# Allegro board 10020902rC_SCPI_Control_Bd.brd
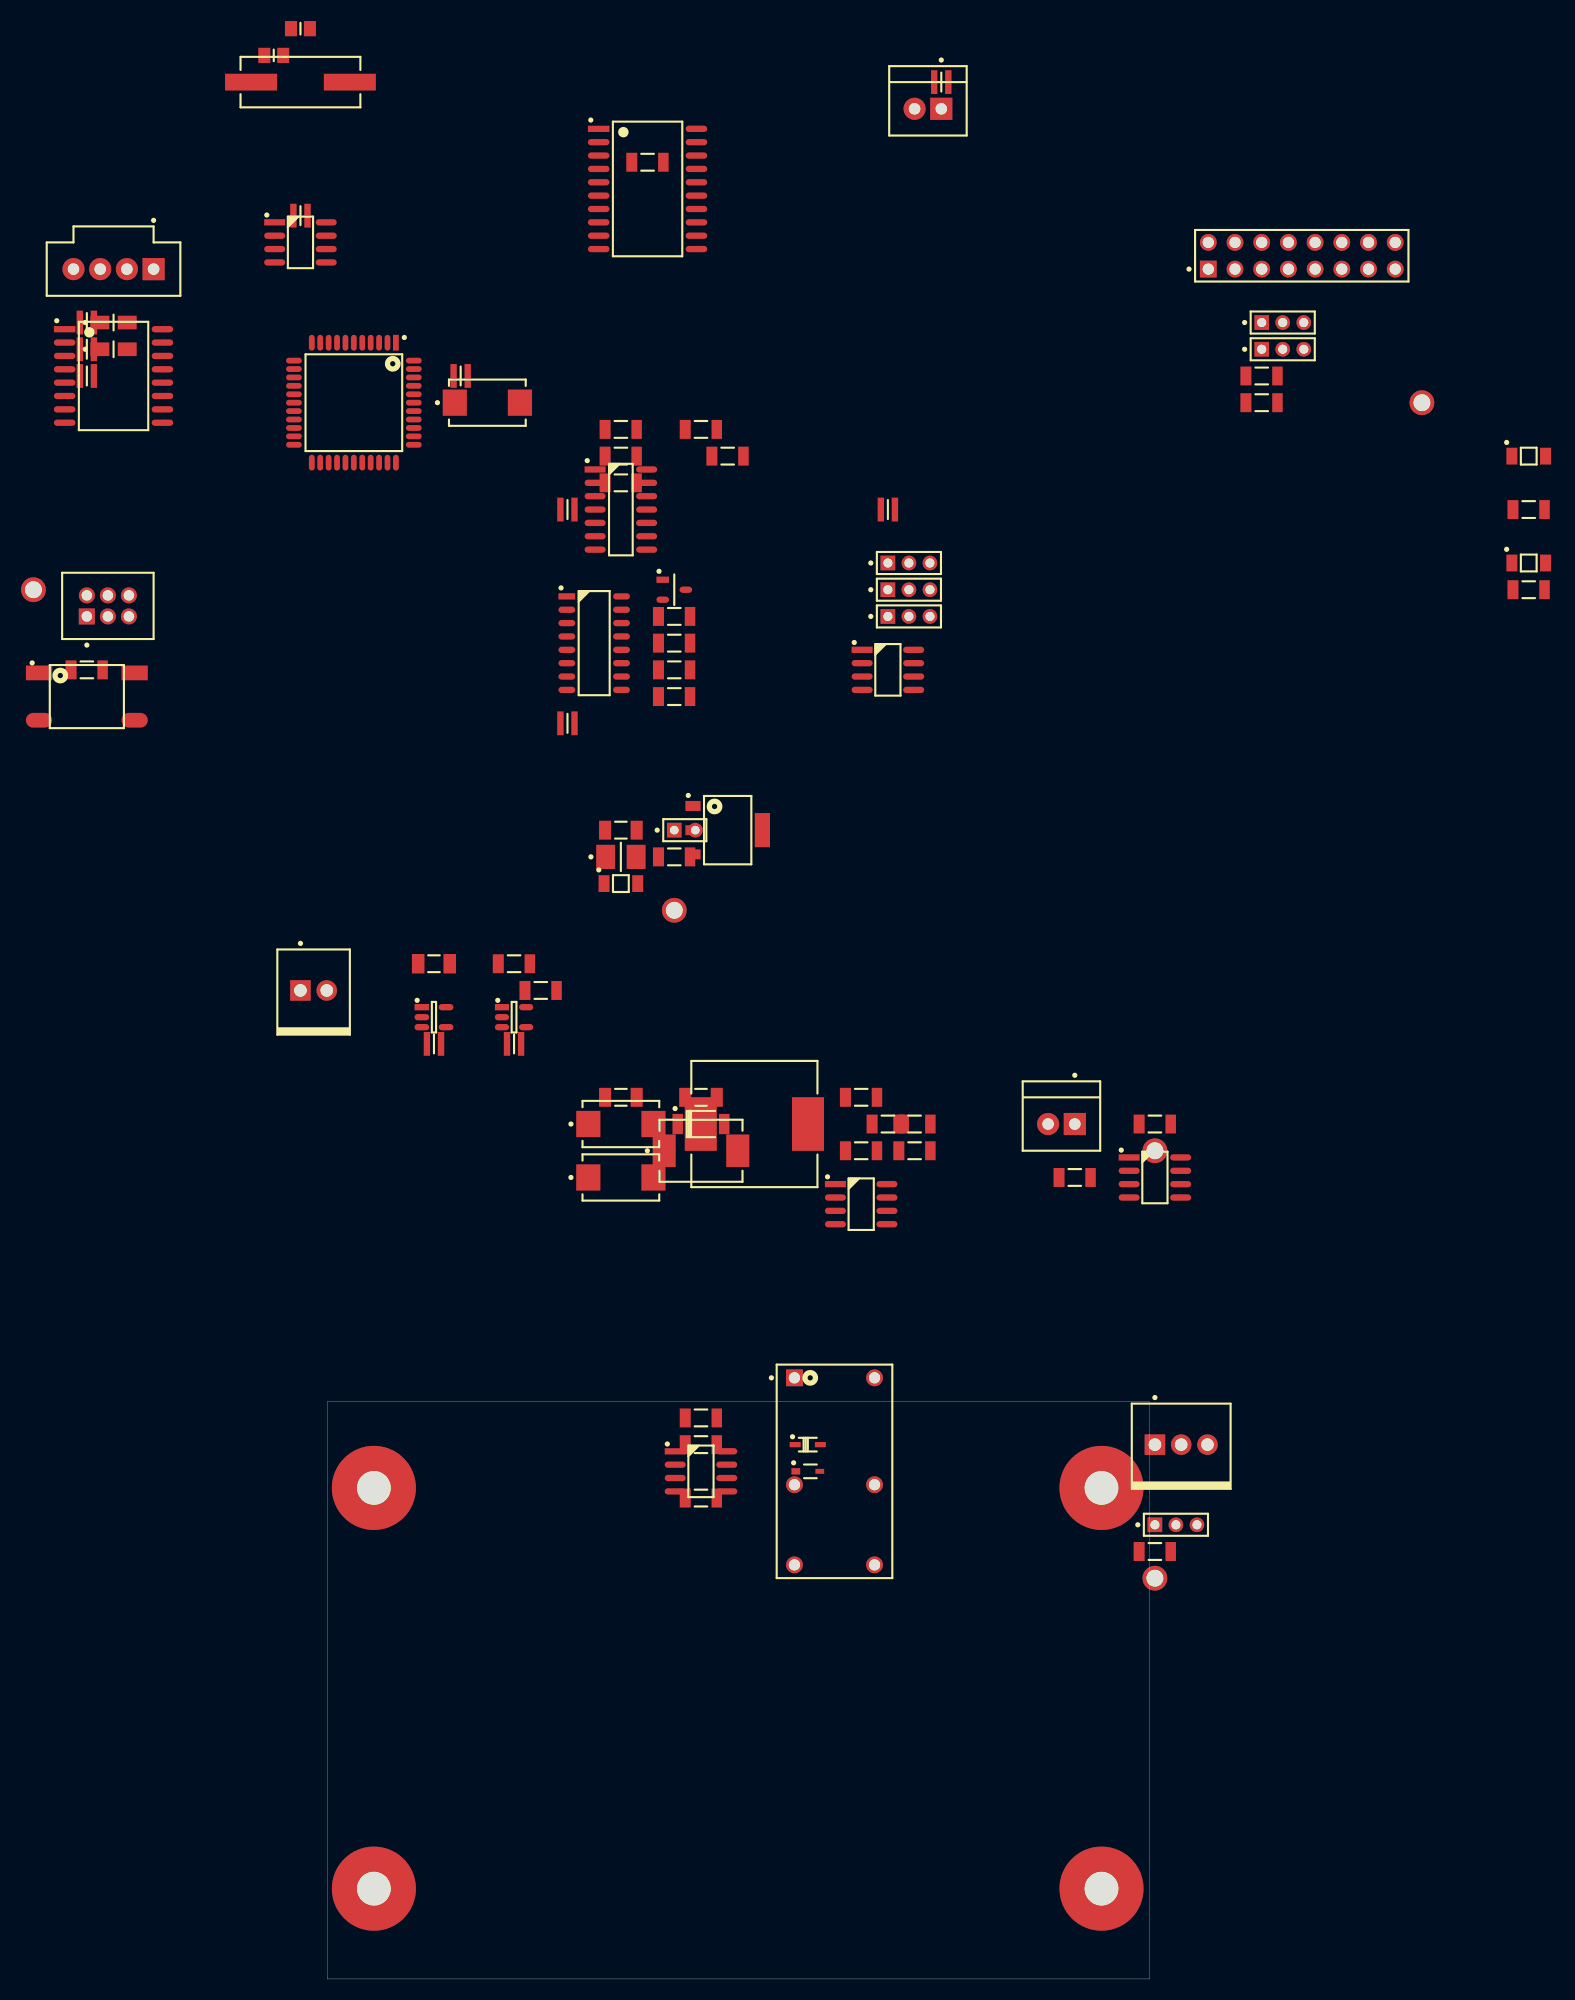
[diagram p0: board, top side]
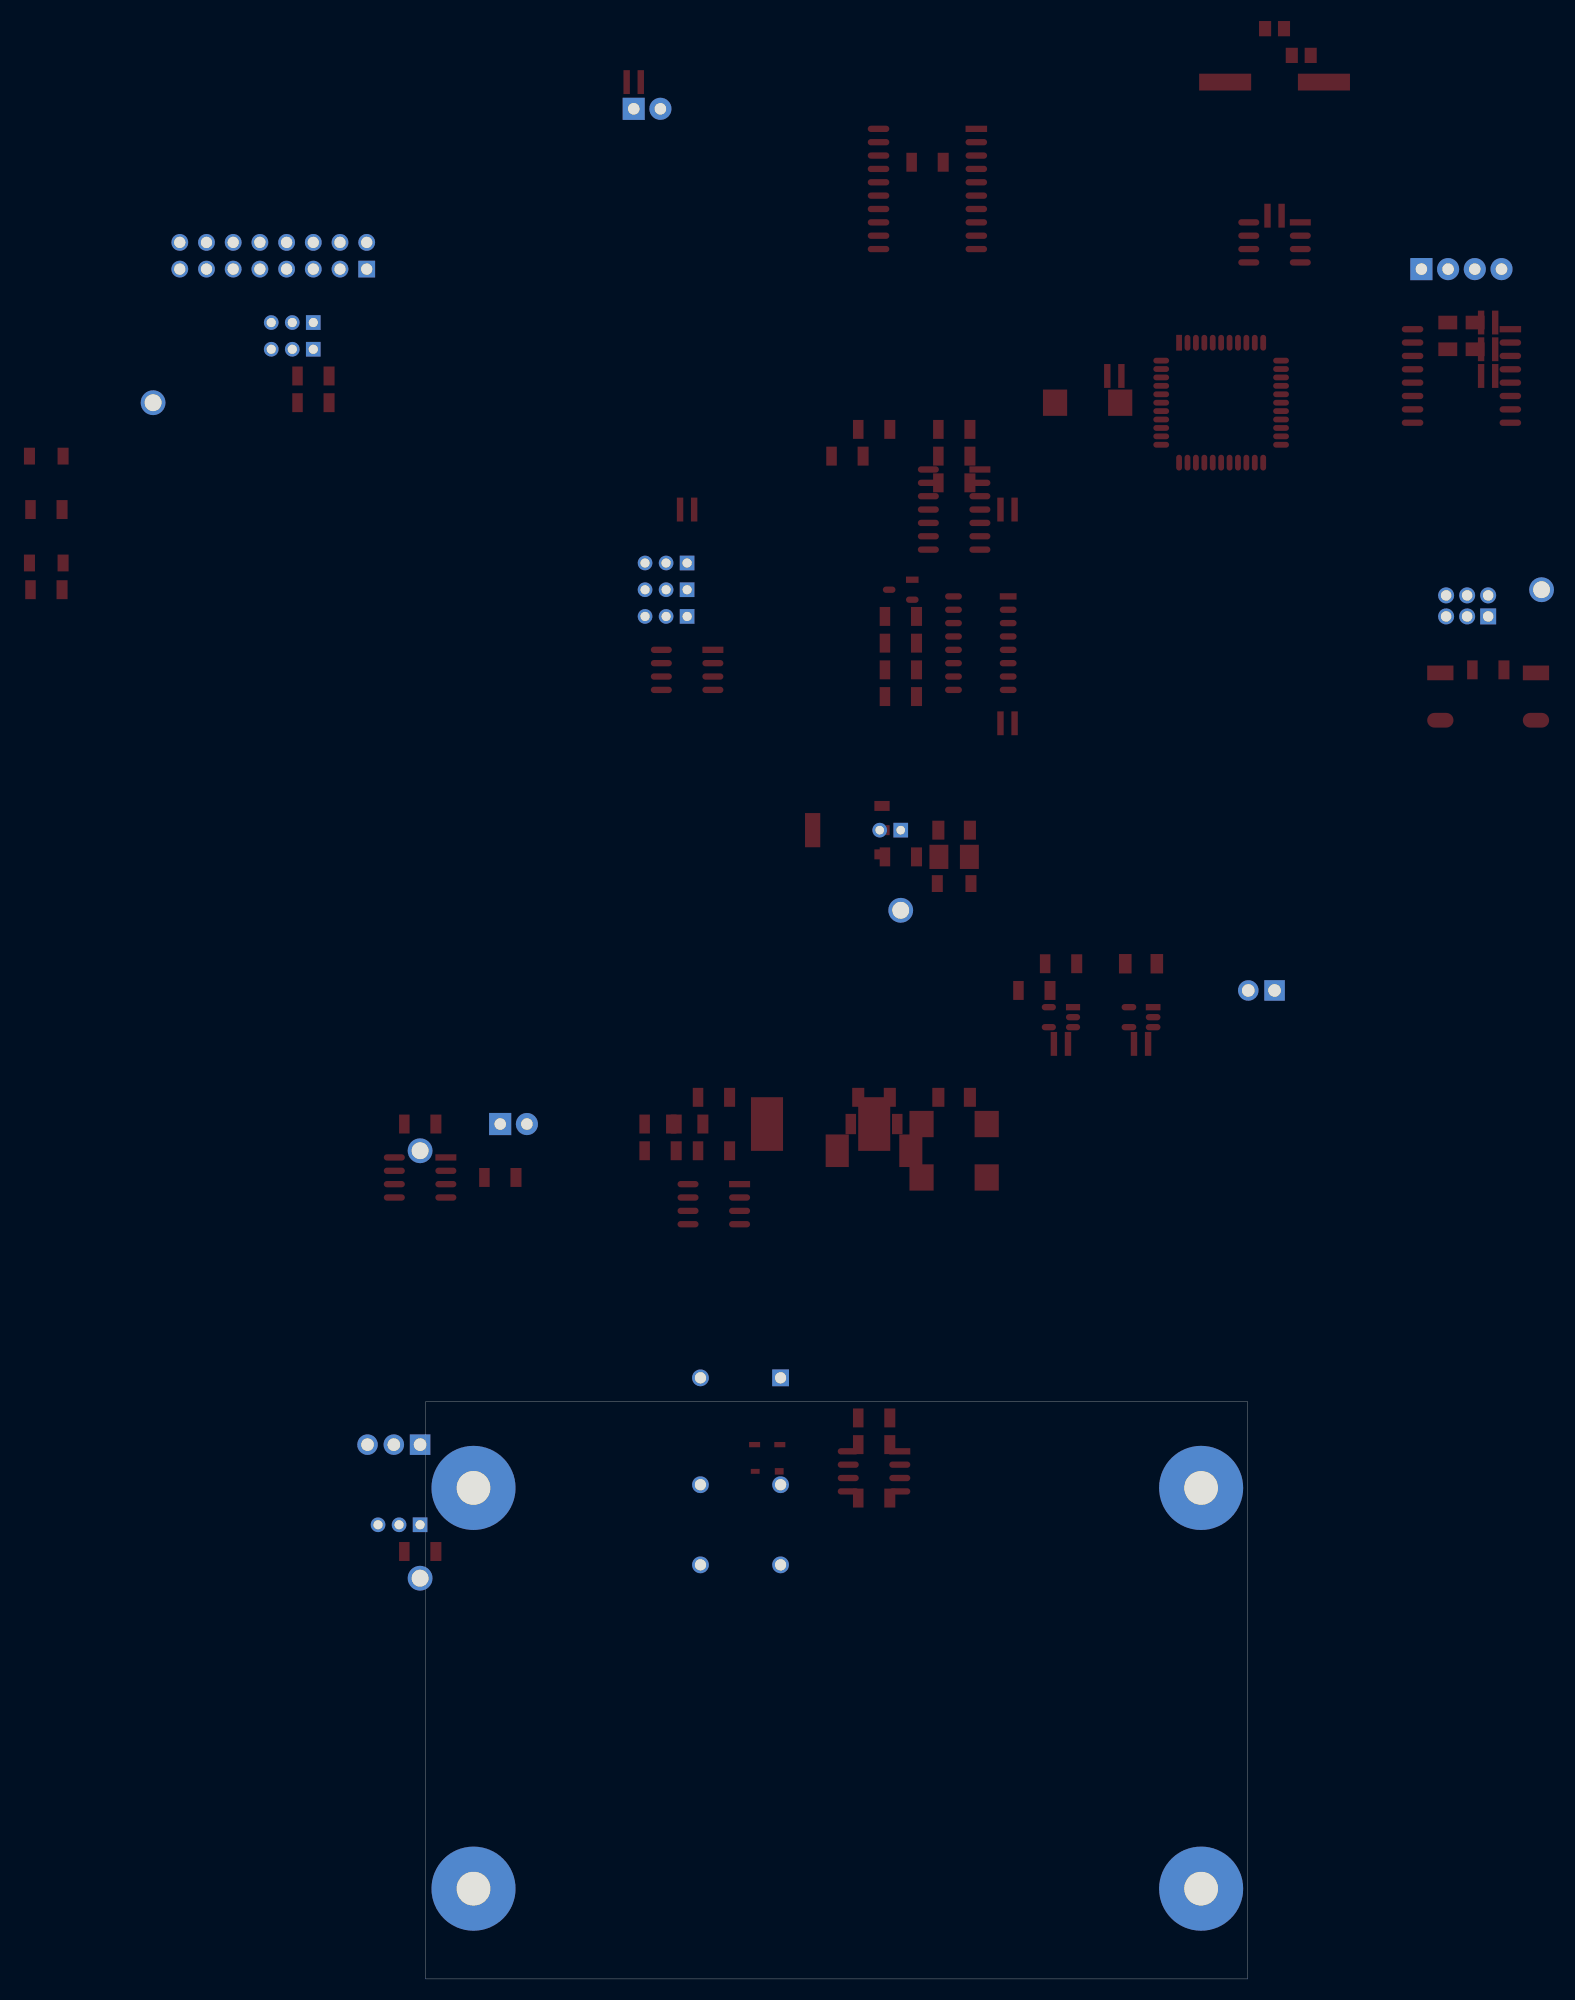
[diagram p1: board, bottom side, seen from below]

Outline 78.23 x 54.86 mm; copper layers: TOP, BOTTOM. Coordinates in mm from the lower left corner of the outline.
Outline path: 0,54.86 0,0 78.23,0 78.23,54.86 0,54.86

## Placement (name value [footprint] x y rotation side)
C1  0.1uF  [CAPC1320X76N]  12.7 152.4 0 top
C2  15pF  [CAPC2012X88N]  -2.54 185.42 0 top
C3  15pF  [CAPC2012X88N]  -5.08 182.88 0 top
C4  0.1uF  [CAPC1320X76N]  -22.86 157.48 0 top
C5  0.1uF  [CAPC1320X76N]  -22.86 154.94 0 top
C6  0.1uF  [CAPC1320X76N]  -22.86 152.4 0 top
C7  0.1uF  [CAPMP3216X180N]  -20.32 157.48 0 top
C8  0.1uF  [CAPMP3216X180N]  -20.32 154.94 0 top
C9  10uF  [CAPMP7343X310N]  15.24 149.86 0 top
C10  0.1uF  [CAPC1320X76N]  -2.54 167.64 0 top
C11  0.1uF  [CAPC1320X76N]  53.34 139.7 0 top
C12  0.1uF  [CAPC1320X76N]  22.86 139.7 0 top
C13  0.1uF  [CAPC1320X76N]  22.86 119.38 0 top
C14  0.1uF  [CAPC1320X76N]  58.42 180.34 0 top
C15  1.0uF  [CAPC3216X110N]  27.94 109.22 0 top
C16  10uF  [CAPMP3528X120N]  27.94 106.68 0 top
C17  0.1uF  [CAPC1320X76N]  10.16 88.9 0 top
C18  0.10uF  [CAPC3216X180N]  27.94 83.82 0 top
C19  100uF  [CAPMP7343X430N]  27.94 81.28 0 top
C20  68uF  [CAPMP7343X310N]  27.94 76.2 0 top
C21  0.10uF  [CAPC3216X180N]  35.56 83.82 0 top
C22  0.1uF  [CAPC1320X76N]  17.78 88.9 0 top
D1  LTST-C150KGKT  [LED_LTST-C150XXX]  114.3 144.78 0 top
D2  LTST-C150KGKT  [LED_LTST-C150XXX]  114.3 134.62 0 top
D3  LTST-C150KGKT  [LED_LTST-C150XXX]  27.94 104.14 0 top
D4  PMEG3050EP,115  [SODFL4725X110N]  35.56 81.28 0 top
D5  B550C-13-F  [DIOM7959X250N]  35.56 78.74 0 top
D6  BZX384-C3V3,115  [SOD2513X110N]  45.72 50.8 0 top
D7  DB2J31700L  [SODFL2513X80N]  45.72 48.26 0 top
J1  68602-116HLF  [HDRV16W64P254_2X8_858H]  83.82 162.56 0 top
J2  87831-0620  [MOLEX_87831-0620]  -22.86 129.54 0 top
J3  70543-0003  [MOLEX_70543-4PIN]  -20.32 162.56 0 top
J4  70543-0001  [MOLEX_70543-2PIN]  58.42 177.8 0 top
J5  1881558  [PHOENIX_1881558]  -2.54 93.98 0 top
J6  70543-0001  [MOLEX_70543-2PIN]  71.12 81.28 0 top
J7  1881561  [PHOENIX_1881561]  78.74 50.8 0 top
JP2  951103-8622-AR  [HDRV3W50P200_1X3_H590]  88.9 157.48 0 top
JP3  951103-8622-AR  [HDRV3W50P200_1X3_H590]  88.9 154.94 0 top
JP4  951103-8622-AR  [HDRV3W50P200_1X3_H590]  53.34 134.62 0 top
JP5  951103-8622-AR  [HDRV3W50P200_1X3_H590]  53.34 132.08 0 top
JP6  951103-8622-AR  [HDRV3W50P200_1X3_H590]  53.34 129.54 0 top
JP7  951102-8622-AR  [HDRV2W50P200_1X2_H590]  33.02 109.22 0 top
JP8  951103-8622-AR  [HDRV3W50P200_1X3_H590]  78.74 43.18 0 top
K1  DSP2A-DC12V  [RELAY_DSP2A-NIL-XXXX]  48.26 48.26 0 top
L1  27uH  [IND_74770127]  40.64 81.28 0 top
NOREF  -  [unnamed]  4.45 8.59 0 top
NOREF#2  -  [unnamed]  73.66 8.59 0 top
NOREF#3  -  [unnamed]  4.45 46.69 0 top
NOREF#4  -  [#2]  -50.8 -76.2 0 top
NOREF#5  -  [unnamed]  73.66 46.69 0 top
Q1  BC847CLT1G  [SOT95P237X111-3N_132]  33.02 132.08 0 top
R1  10.0K  [RESC3216X60N]  27.94 147.32 0 top
R2  10.0K  [RESC3216X60N]  27.94 144.78 0 top
R3  10.0K  [RESC3216X60N]  27.94 142.24 0 top
R4  10.0K  [RESC3216X60N]  -22.86 124.46 0 top
R5  1.00K  [RESC3216X60N]  88.9 152.4 0 top
R6  3.32K  [RESC3216X60N]  33.02 129.54 0 top
R7  6.81K  [RESC3216X60N]  33.02 124.46 0 top
R8  110  [RESC3216X60N]  114.3 139.7 0 top
R9  100.0K  [RESC3216X60N]  88.9 149.86 0 top
R10  1.00K  [RESC3216X60N]  33.02 127 0 top
R11  10.0K  [RESC3216X60N]  33.02 121.92 0 top
R13  110  [RESC3216X60N]  114.3 132.08 0 top
R14  100.0K  [RESC3216X60N]  30.48 172.72 0 top
R15  10.0K  [RESC3216X60N]  35.56 147.32 0 top
R16  10.0K  [RESC3216X60N]  38.1 144.78 0 top
R17  59  [RESC3216X60N]  33.02 106.68 0 top
R18  0.02  [RESC3216X89N]  10.16 96.52 0 top
R19  121.0K  [RESC3216X60N]  17.78 96.52 0 top
R20  22.1K  [RESC3216X60N]  20.32 93.98 0 top
R21  10.0K  [RESC3216X60N]  71.12 76.2 0 top
R22  1.00M  [RESC3216X60N]  50.8 78.74 0 top
R23  TBD  [RESC3216X60N]  50.8 83.82 0 top
R24  10.0K  [RESC3216X60N]  78.74 81.28 0 top
R25  383.0K  [RESC3216X60N]  53.34 81.28 0 top
R26  36.5K  [RESC3216X60N]  55.88 81.28 0 top
R27  13.3K  [RESC3216X60N]  55.88 78.74 0 top
R28  100.0K  [RESC3216X60N]  78.74 40.64 0 top
R29  10.0K  [RESC3216X60N]  35.56 53.34 0 top
R30  10.0K  [RESC3216X60N]  35.56 50.8 0 top
R31  10.0K  [RESC3216X60N]  35.56 45.72 0 top
SW1  SWT6-V2M  [SW_SWT6-M]  -22.86 121.92 0 top
TP1  YELLOW  [TP_KEYSTONE_5000S_COMP]  33.02 101.6 0 top
TP2  RED  [TP_KEYSTONE_5000S_COMP]  -27.94 132.08 0 top
TP3  BLACK  [TP_KEYSTONE_5000S_COMP]  104.14 149.86 0 top
TP4  ORANGE  [TP_KEYSTONE_5000S_COMP]  78.74 78.74 0 top
TP5  GREEN  [TP_KEYSTONE_5000S_COMP]  78.74 38.1 0 top
U1  SN74LS07D  [SOIC127P600X175-14N]  27.94 139.7 0 top
U2  PIC24FJ64GA104-I/PT  [QFP80P1200X1200X120-44N]  2.54 149.86 270 top
U3  74HC4050D,653  [SOIC127P600X175-16N]  25.4 127 0 top
U4  MAX3232IDWR  [SOIC127P1030X265-16N]  -20.32 152.4 0 top
U5  DS3234S#  [SOIC127P1032X265-20N]  30.48 170.18 0 top
U6  SST25VF080B-80-4I-SAE  [SOIC127P600X175-8N]  -2.54 165.1 0 top
U7  24AA01-I/SN  [SOIC127P600X175-8N]  53.34 124.46 0 top
U8  MIC5209-3.3YS  [SOT230P700X180-4N]  38.1 109.22 0 top
U9  MAX4372FEUK+T  [SOT95P280X145-5N]  10.16 91.44 0 top
U10  AD8603AUJZ  [SOT95P280X100-5N]  17.78 91.44 0 top
U11  MAX5035DASA+  [SOIC127P600X175-8N]  50.8 73.66 0 top
U12  IRF7309TRPBF  [SOIC127P600X175-8N]  78.74 76.2 0 top
U13  IRF7309TRPBF  [SOIC127P600X175-8N]  35.56 48.26 0 top
Y1  3.6864MHz  [XTAL1140X480X430N]  -2.54 180.34 0 top

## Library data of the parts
C1-C6 C10-C15 C17 C18 C21 C22 = CAP
C7-C9 C16 C19 C20 = CAP_P
D1-D3 = LED
D4 D5 = DIODE_SCHOTTKY
D6 = DIODE_ZENER
D7 = DIODE
J1 = CON16
J2 = CON6
J3 = CON4
J4-J6 = CON2
J7 = CON3
JP2-JP6 JP8 = JUMPER3PIN_CENTER-TAP
JP7 = JUMPER
K1 = RELAY_DSP2A-NIL-XXXX
L1 = IND_FERRITE
Q1 = BJT_NPN_BEC
R1-R11 R13-R31 = RES
SW1 = SW_SPST_13_24
TP1-TP5 = TESTPOINT
U1 = SN74LS07
U2 = PIC24FJxxGA104
U3 = 74HC4050
U4 = MAX3232
U5 = DS3234Sx
U6 = SST25VF080B
U7 = 24AA01SN
U8 = MIC5209-x.xxS
U9 = MAX4372xEUK-T_SYM-MOD1
U10 = AD8603
U11 = MAX5035
U12 U13 = IRF7309
Y1 = CRYSTAL

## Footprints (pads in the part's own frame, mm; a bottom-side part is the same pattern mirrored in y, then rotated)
CAPC1320X76N
  rect 0.61x2.271 smd: 1(-0.671,0) 2(0.671,0)
CAPC2012X88N
  rect 1.151x1.45 smd: 1(-0.899,0) 2(0.899,0)
CAPC3216X110N
  rect 1.151x1.801 smd: 1(-1.501,0) 2(1.501,0)
CAPC3216X180N
  rect 1.151x1.801 smd: 1(-1.501,0) 2(1.501,0)
CAPMP3216X180N
  rect 1.801x1.3 smd: 1(-1.3,0) 2(1.3,0)
CAPMP3528X120N
  rect 1.801x2.301 smd: 1(-1.45,0) 2(1.45,0)
CAPMP7343X310N
  rect 2.301x2.499 smd: 1(-3.099,0) 2(3.099,0)
CAPMP7343X430N
  rect 2.301x2.499 smd: 1(-3.099,0) 2(3.099,0)
DIOM7959X250N
  rect 2.2x3.099 smd: A(3.5,0) C(-3.5,0)
HDRV2W50P200_1X2_H590
  rect 1.397x1.397 hole 0.813: 1(0,0)
  round 1.397 hole 0.813: 2(1.999,0)
HDRV3W50P200_1X3_H590
  rect 1.397x1.397 hole 0.864: 1(0,0)
  round 1.397 hole 0.864: 2(1.999,0) 3(4,0)
HDRV16W64P254_2X8_858H
  rect 1.6x1.6 hole 1.067: 1(0,0)
  round 1.6 hole 1.067: 2(0,2.54) 3(2.54,0) 4(2.54,2.54) 5(5.08,0) 6(5.08,2.54) 7(7.62,0) 8(7.62,2.54) 9(10.16,0) 10(10.16,2.54) 11(12.7,0) 12(12.7,2.54) 13(15.24,0) 14(15.24,2.54) 15(17.78,0) 16(17.78,2.54)
IND_74770127
  rect 3.051x5.1 smd: 1(-5.1,0) 2(5.1,0)
LED_LTST-C150XXX
  rect 1.049x1.6 smd: A(1.6,0) C(-1.6,0)
MOLEX_70543-2PIN
  rect 2.108x2.108 hole 1.092: 1(0,0)
  round 2.108 hole 1.092: 2(-2.54,0)
MOLEX_70543-4PIN
  rect 2.108x2.108 hole 1.092: 1(3.81,0)
  round 2.108 hole 1.092: 2(1.27,0) 3(-1.27,0) 4(-3.81,0)
MOLEX_87831-0620
  rect 1.524x1.524 hole 0.991: 1(0,0)
  round 1.524 hole 0.991: 2(0,1.999) 3(1.999,0) 4(1.999,1.999) 5(4,0) 6(4,1.999)
PHOENIX_1881558
  rect 1.956x1.956 hole 1.194: 1(0,0)
  round 1.956 hole 1.194: 2(2.499,0)
PHOENIX_1881561
  rect 1.956x1.956 hole 1.194: 1(0,0)
  round 1.956 hole 1.194: 2(2.499,0) 3(5.001,0)
QFP80P1200X1200X120-44N
  rect 1.501x0.551 smd: 1(-5.7,4)
  oval 1.501x0.551 smd: 2(-5.7,3.2) 3(-5.7,2.4) 4(-5.7,1.6) 5(-5.7,0.8) 6(-5.7,0) 7(-5.7,-0.8) 8(-5.7,-1.6) 9(-5.7,-2.4) 10(-5.7,-3.2) 11(-5.7,-4) 23(5.7,-4) 24(5.7,-3.2) 25(5.7,-2.4) 26(5.7,-1.6) 27(5.7,-0.8) 28(5.7,0) 29(5.7,0.8) 30(5.7,1.6) 31(5.7,2.4) 32(5.7,3.2) 33(5.7,4)
  oval 0.551x1.501 smd: 12(-4,-5.7) 13(-3.2,-5.7) 14(-2.4,-5.7) 15(-1.6,-5.7) 16(-0.8,-5.7) 17(0,-5.7) 18(0.8,-5.7) 19(1.6,-5.7) 20(2.4,-5.7) 21(3.2,-5.7) 22(4,-5.7) 34(4,5.7) 35(3.2,5.7) 36(2.4,5.7) 37(1.6,5.7) 38(0.8,5.7) 39(0,5.7) 40(-0.8,5.7) 41(-1.6,5.7) 42(-2.4,5.7) 43(-3.2,5.7) 44(-4,5.7)
RELAY_DSP2A-NIL-XXXX
  rect 1.6x1.6 hole 1.067: 1(-3.81,8.89)
  round 1.6 hole 1.067: 5(-3.81,-1.27) 8(-3.81,-8.89) 9(3.81,-8.89) 12(3.81,-1.27) 16(3.81,8.89)
RESC3216X60N
  rect 1.049x1.801 smd: 1(-1.501,0)
  rect 1.001x1.801 smd: 2(1.501,0)
RESC3216X89N
  rect 1.199x1.849 smd: 1(-1.501,0) 2(1.501,0)
SOD2513X110N
  rect 1.049x0.5 smd: A(1.199,0) C(-1.199,0)
SODFL2513X80N
  rect 0.841x0.47 smd: A(1.14,0)
  rect 0.841x0.62 smd: C(-1.14,0)
SODFL4725X110N
  rect 1.001x1.93 smd: A(2.21,0) C(-2.21,0)
SOIC127P600X175-8N
  rect 1.999x0.599 smd: 1(-2.451,1.905)
  oval 1.999x0.599 smd: 2(-2.451,0.635) 3(-2.451,-0.635) 4(-2.451,-1.905) 5(2.451,-1.905) 6(2.451,-0.635) 7(2.451,0.635) 8(2.451,1.905)
SOIC127P600X175-14N
  rect 1.999x0.599 smd: 1(-2.451,3.81)
  oval 1.999x0.599 smd: 2(-2.451,2.54) 3(-2.451,1.27) 4(-2.451,0) 5(-2.451,-1.27) 6(-2.451,-2.54) 7(-2.451,-3.81) 8(2.451,-3.81) 9(2.451,-2.54) 10(2.451,-1.27) 11(2.451,0) 12(2.451,1.27) 13(2.451,2.54) 14(2.451,3.81)
SOIC127P600X175-16N
  rect 1.6x0.599 smd: 1(-2.601,4.445)
  oval 1.6x0.599 smd: 2(-2.601,3.175) 3(-2.601,1.905) 4(-2.601,0.635) 5(-2.601,-0.635) 6(-2.601,-1.905) 7(-2.601,-3.175) 8(-2.601,-4.445) 9(2.601,-4.445) 10(2.601,-3.175) 11(2.601,-1.905) 12(2.601,-0.635) 13(2.601,0.635) 14(2.601,1.905) 15(2.601,3.175) 16(2.601,4.445)
SOIC127P1030X265-16N
  rect 2.05x0.599 smd: 1(-4.651,4.445)
  oval 2.05x0.599 smd: 2(-4.651,3.175) 3(-4.651,1.905) 4(-4.651,0.635) 5(-4.651,-0.635) 6(-4.651,-1.905) 7(-4.651,-3.175) 8(-4.651,-4.445) 9(4.651,-4.445) 10(4.651,-3.175) 11(4.651,-1.905) 12(4.651,-0.635) 13(4.651,0.635) 14(4.651,1.905) 15(4.651,3.175) 16(4.651,4.445)
SOIC127P1032X265-20N
  rect 2.05x0.599 smd: 1(-4.651,5.715)
  oval 2.05x0.599 smd: 2(-4.651,4.445) 3(-4.651,3.175) 4(-4.651,1.905) 5(-4.651,0.635) 6(-4.651,-0.635) 7(-4.651,-1.905) 8(-4.651,-3.175) 9(-4.651,-4.445) 10(-4.651,-5.715) 11(4.651,-5.715) 12(4.651,-4.445) 13(4.651,-3.175) 14(4.651,-1.905) 15(4.651,-0.635) 16(4.651,0.635) 17(4.651,1.905) 18(4.651,3.175) 19(4.651,4.445) 20(4.651,5.715)
SOT95P237X111-3N_132
  rect 1.199x0.599 smd: 1(-1.1,0.95)
  oval 1.199x0.599 smd: 2(-1.1,-0.95) 3(1.1,0)
SOT95P280X100-5N
  rect 1.349x0.599 smd: 1(-1.151,0.95)
  oval 1.349x0.599 smd: 2(-1.151,0) 3(-1.151,-0.95) 4(1.151,-0.95) 5(1.151,0.95)
SOT95P280X145-5N
  rect 1.4x0.599 smd: 1(-1.151,0.95)
  oval 1.4x0.599 smd: 2(-1.151,0) 3(-1.151,-0.95) 4(1.151,-0.95) 5(1.151,0.95)
SOT230P700X180-4N
  rect 1.45x0.95 smd: 1(-3.299,2.301) 2(-3.299,0) 3(-3.299,-2.301)
  rect 1.45x3.251 smd: 4(3.299,0)
SW_SWT6-M
  rect 2.499x1.4 smd: 1(-4.549,2.25) 3(4.549,2.25)
  oval 2.499x1.4 smd: 2(-4.549,-2.25) 4(4.549,-2.25)
TP_KEYSTONE_5000S_COMP
  round 2.362 hole 1.6: 1(0,0)
unnamed
  round 8.001 hole 3.2: (0,0)
XTAL1140X480X430N
  rect 4.95x1.6 smd: 1(-4.699,0) 2(4.699,0)

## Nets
3.3V: C1.1 C6.1 C10.2 C11.1 C12.1 C13.1 C14.1 C16.1 C17.1 C22.1 J2.2 JP6.1 JP7.1 JP8.1 K1.8(B1) R1.2 R2.2 R3.2 R4.2 R9.1 R14.2 R15.2 R16.2 TP1.1(TP) U1.14(VCC) U2.17(AVDD) U2.28(VDD_1) U2.40(VDD_2) U3.1(VCC) U4.16(VCC) U5.4(VCC) U6.8(VDD) U7.8(VCC) U8.3(OUT) U9.3(VCC) U10.5(V+)
GND_SIGNAL: C1.2 C2.2 C3.2 C6.2 C7.1 C8.2 C9.2 C10.1 C11.2 C12.2 C13.2 C14.2 C15.2 C16.2 C17.2 C19.2 C20.2 C21.2 C22.2 D1.C D2.C D3.C D5.A D6.C J1.13 J1.14 J2.3 J3.3 J3.4 J4.2 J5.2 J6.2 J7.3 JP2.3 JP3.3 JP6.3 JP8.3 K1.16(COIL-) Q1.2(E) R5.1 R7.2 R11.2 R20.2 R24.1 R25.2 R27.2 R29.1 R31.1 SW1.2 SW1.4 TP3.1(TP) U1.7(GND) U1.9(4A) U1.11(5A) U1.13(6A) U2.6(DISVREG) U2.16(AVSS) U2.29(VSS_1) U2.39(VSS_2) U3.7(3A) U3.8(GND) U3.9(4A) U3.11(5A) U3.14(6A) U4.8(R2IN) U4.10(DIN2) U4.15(GND) U5.2(NC2) U5.7(NC7) U5.8(NC8) U5.9(NC9) U5.10(NC10) U5.11(NC11) U5.12(NC12) U5.13(NC13) U5.14(NC14) U5.15(GND) U6.4(VSS) U7.1(A0) U7.2(A1) U7.3(A2) U7.4(GND) U8.2(GND) U8.4(\) U9.1(GND) U10.2(V-) U11.3(SGND) U11.6(GND) U12.1(S1) U13.1(S1)
BATT: C15.1 C19.1 K1.12(A2) R18.2 R19.1 R22.1 R30.2 U8.1(IN) U9.5(RS-) U11.7(VIN) U13.3(S2)
BATT_CURR: U2.23(AN4/C1INB/RP2/SDA2/CN6/RB2) U9.2(OUT)
BATT_VOLT: U2.24(AN5/C1INA/RP3/SCL2/CN7/RB3) U10.1(OUT) U10.4(IN-)
CAM_ON_OFF: R24.2 U2.19(AN0/C3INC/VREF+/CN2/CTED1/RA0) U12.2(G1)
LED_CNTL: R31.2 U2.3(RP23/CN17/PMA0/RC7) U13.2(G1)
LED_STATE: K1.5(A1) R29.2 U2.4(RP24/CN20/PMA5/RC8)
LED_TRIG: J7.1 R28.2 U2.2(RP22/CN18/PMA1/RC6)
N14907254: J2.1 R4.1 SW1.1 SW1.3 U2.18(MCLR*)
N14907334: U1.1(1A) U2.25(AN6/RP16/CN8/RC0)
N14907346: U2.26(AN7/RP17/CN9/RC1) U3.2(1Y)
N14907358: U1.3(2A) U2.27(AN8/RP18/PMA2/CN10/RC2)
N14907370: U1.5(3A) U2.36(RP19/CN28/PMBE/RC3)
N14907460: Q1.1(B) R10.2 R11.1
N14907464: R10.1 U2.38(RP21/CN26/PMA3/RC5)
N14907857: J1.2 Q1.3(C)
N14907883: J1.3 R1.1 U1.2(1Y)
N14907926: J1.5 U3.3(1A)
N14907967: J1.6 R2.1 U1.4(2Y)
N14907987: J1.7 R3.1 U1.6(3Y)
N14908751: JP2.1 R9.2
N14908758: JP3.1
N14908817: J1.1 JP3.2
N14908823: J1.4 JP2.2
N14908912: JP4.2 U7.5(SDA)
N14908949: JP5.2 U7.6(SCL)
N14908956: JP4.1 R15.1 U2.1(RP9/SDA1/CN21/PMD3/RB9)
N14909000: JP5.1 R16.1 U2.44(RP8/SCL1/CN22/PMD4/RB8)
N14909094: J1.11 JP4.3
N14909112: J1.12 JP5.3
N14910852: C3.1 U2.31(OSCO/CLKO/CN29/RA3) Y1.2
N14910856: C2.1 U2.30(OSCI/CLKI/C1IND/CN30/RA2) Y1.1
N14911169: C4.1 U4.1(C+)
N14911173: C5.1 U4.4(C2+)
N14911187: C4.2 U4.3(C1-)
N14911204: C5.2 U4.5(C2-)
N14911399: C7.2 U4.6(V-)
N14911406: C8.1 U4.2(V+)
N14911585: R6.1 R7.1 U3.5(2A)
N14911707: J1.9 J1.10 R6.2
N14911875: J1.8 R5.2
N14916159: JP6.2 U7.7(WP)
N14918456: J3.2 U4.14(DOUT1)
N14918460: J3.1 U4.13(R1IN)
N14934806: U2.14(AN10/C3INB/CVREF/RTCC/RP14/CN12) U4.12(R1OUT)
N14934816: U2.15(AN9/C3INA/RP15/CN11/RB15) U4.11(DIN1)
N14937836: J4.1 U5.16(VBAT)
N14938943: D1.A R8.2
N14940001: C9.1 U2.7(VCAP/VDDCORE)
N14968686: D2.A R13.2
N14976351: U2.10(AN12/RP12/CN14/PMD0/RB12) U5.18(SCLK_1) U5.20(SCLK_0) U6.6(SCK)
N14991516: D4.C R21.1 TP4.1(TP) U12.3(S2)
N14991548: J6.1 U12.5(D2B) U12.6(D2A)
N14991564: R21.2 U12.4(G2) U12.7(D1B) U12.8(D1A)
N14993015: D3.A R17.2
N14993095: J5.1 R18.1 TP2.1(TP) U9.4(RS+)
N14993373: R19.2 R20.1 U10.3(IN+)
N14997505: D7.C(CATHODE) K1.1(COIL+) U13.5(D2B) U13.6(D2A)
N14997509: R30.1 U13.4(G2) U13.7(D1B) U13.8(D1A)
N14997545: J7.2 K1.9(B2) TP5.1(TP)
N14997611: JP8.2 R28.1
N14997833: D6.A D7.A(ANODE)
N15001299: J2.5 U2.22(PGEC1/AN3/C2INA/RP1/CN5/RB1)
N15001311: J2.4 U2.21(PGED1/AN2/C2INB/RP0/CN4/RB0)
N15003009: U2.37(RP20/CN25/PMA4/RC4) U3.4(2Y)
N15003605: U2.11(AN11/C1INC/RP13/PMRD/REFO/CN13/) U5.1(C\S\)
N15003639: U2.9(PGEC2/RP11/CN15/PMD1/RB11) U5.17(DIN) U6.5(SI)
N15003651: U2.8(PGED2/RP10/CN16/PMD2/RB10) U5.19(DOUT) U6.2(SO)
N15003663: U2.12(TMS/PMA10/RA10) U5.6(R\S\T\)
N15007328: JP7.2 R17.1
N15010506: C18.2 D5.C L1.1 U11.8(LX)
N15010522: C20.1 D4.A L1.2 R23.1
N15010535: R26.2 R27.1 U11.4(FB)
N15010979: C21.1 U11.2(VD)
N15011317: C18.1 U11.1(BST)
N15011830: R22.2 R25.1 U11.5(ON/\O\F\F\)
N15012683: R13.1 U2.33(SOSCI/C1IND/RP4/CN1/RB4)
N15013353: R8.1
N15018313: U2.5(RP25/CN19/PMA6/RC9) U6.1(CE#)
N15018357: U2.35(TDI/PMA9/RA9) U6.7(HOLD#)
N15018369: U2.32(TDO/PMA8/RA8) U6.3(WP#)
N15023556: R14.1 U2.34(SOSCO/SCLK1/T1CK/C2INC/CN0/RA4) U5.5(I\N\T\/SQW)
N15039082: R23.2 R26.1

Pads without a net: J1 15 16; J2 6; U1 8 10 12; U2 13 20 41 42 43; U3 6 10 12 13 15 16; U4 7 9; U5 3
